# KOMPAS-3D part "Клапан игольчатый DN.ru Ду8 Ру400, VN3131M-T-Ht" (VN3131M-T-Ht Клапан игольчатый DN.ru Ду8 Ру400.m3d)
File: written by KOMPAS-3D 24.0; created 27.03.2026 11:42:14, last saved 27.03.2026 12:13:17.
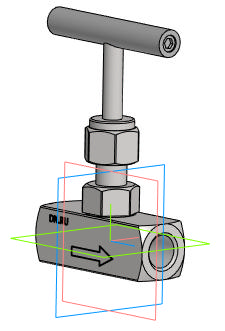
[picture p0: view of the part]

Document properties: Автор: Илья; Полное имя файла: VN3232M-T-Ht Клапан игольчатый DN.ru Ду8 Ру400.cdw

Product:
- Body: Body3  | qty 1
    Масса: 0.248386
- Part/product: Клапан игольчатый DN.ru Ду8 Ру400  | designation VN3131M-T-Ht
    Масса: 0.35
    Раздел спецификации: Прочие изделия
    Форматы листов документа: A4
    Примечание: D090-02129

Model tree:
1. Body3  (labels: Body3)

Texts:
  VN3131M-T-Ht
